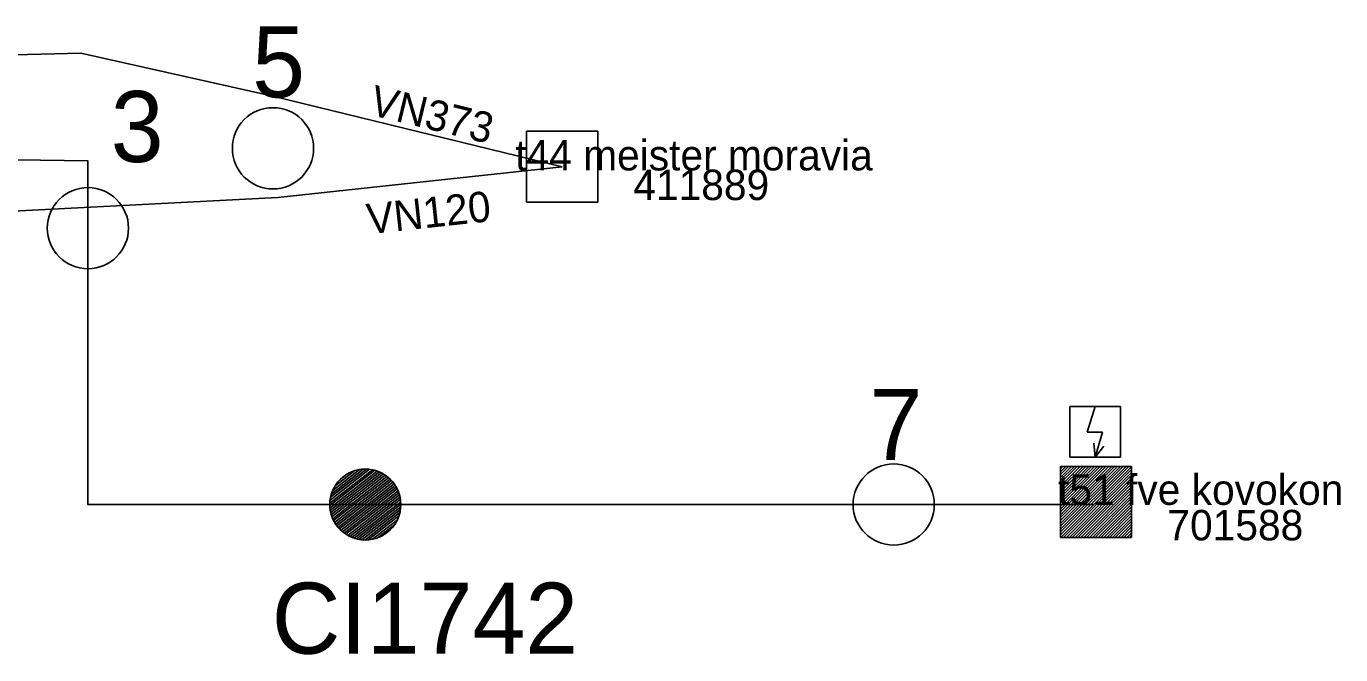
# Model space of a CAD drawing. Extents: x -541654 to -535721, y -1185255 to -1179094.
# Drawn here: x -539460 to -538812, y -1183468 to -1183158 of the extents above; entities that cross this region are included whole.
import ezdxf

# ---------------------------------------------------------------- set-up
doc = ezdxf.new("R2010")
doc.units = 0
for name, color, linetype in [('Default', 7, 'Continuous'), ('Vrstva 1', 7, 'Continuous'), ('Vrstva 2', 7, 'Continuous'), ('Vrstva 20', 7, 'Continuous'), ('Vrstva 3', 7, 'Continuous'), ('Vrstva 4', 7, 'Continuous'), ('Vrstva 47', 7, 'Continuous'), ('Vrstva 5', 7, 'Continuous')]:
    doc.layers.add(name, color=color, linetype=linetype)

# ---------------------------------------------------------------- blocks, each defined once
blk = doc.blocks.new('PS700')
at = {"layer": 'Vrstva 47'}
for points in [[(12.48, 12.51), (-12.52, 12.51)], [(-12.52, 12.51), (-12.52, -12.49)], [(-0.02, 12.51), (-3.96, -0.19)], [(12.48, -12.49), (12.48, 12.51)], [(-3.96, -0.19), (3.52, -0.19)], [(-0.02, -12.49), (-0.71, -5.7)], [(3.52, -0.19), (-0.02, -12.49)], [(-12.52, -12.49), (12.48, -12.49)], [(-0.02, -12.49), (4.31, -7.08)]]:
    blk.add_lwpolyline(points, dxfattribs=at)
blk = doc.blocks.new('PS140')
at = {"layer": 'Default'}
for p, q in [((-17.49, -0.01), (0.01, 17.49)), ((-17.43, -1.37), (1.37, 17.43)), ((-17.42, 1.47), (-1.47, 17.42)), ((-17.29, -2.63), (2.63, 17.29)), ((-17.21, 3.1), (-3.1, 17.21)), ((-17.06, -3.82), (3.82, 17.06)), ((-16.77, -4.95), (4.95, 16.77)), ((-16.77, 4.95), (-4.95, 16.77)), ((-16.42, -6.01), (6.01, 16.42)), ((-16.02, -7.02), (7.02, 16.02)), ((-15.93, 7.2), (-7.2, 15.93)), ((-15.56, -7.98), (7.98, 15.56)), ((-15.06, -8.89), (8.89, 15.06)), ((-14.51, -9.76), (9.76, 14.51)), ((-13.92, -10.58), (10.58, 13.92)), ((-13.75, 10.8), (-10.8, 13.75)), ((-13.29, -11.36), (11.36, 13.29)), ((-12.62, -12.11), (12.11, 12.62)), ((-11.91, -12.81), (12.81, 11.91)), ((-11.15, -13.47), (13.47, 11.15)), ((-10.36, -14.09), (14.09, 10.36)), ((-9.52, -14.67), (14.67, 9.52)), ((-8.64, -15.2), (15.2, 8.64)), ((-7.72, -15.69), (15.69, 7.72)), ((-6.74, -16.13), (16.13, 6.74)), ((-5.72, -16.52), (16.52, 5.72)), ((-4.64, -16.86), (16.86, 4.64)), ((-3.5, -17.13), (17.13, 3.5)), ((-2.29, -17.34), (17.34, 2.29)), ((-1, -17.46), (17.46, 1)), ((0.39, -17.48), (17.48, -0.39)), ((1.91, -17.38), (17.38, -1.91)), ((3.59, -17.11), (17.11, -3.59)), ((5.53, -16.59), (16.59, -5.53)), ((7.96, -15.57), (15.57, -7.96))]:
    blk.add_line(p, q, dxfattribs=at)
blk.add_circle((0, 0), 17.49, dxfattribs=at)
blk = doc.blocks.new('PS800')
at = {"layer": 'Vrstva 2'}
blk.add_circle((0, -0.01), 20, dxfattribs=at)
blk = doc.blocks.new('PS651')
at = {"layer": 'Vrstva 20'}
for points in [[(17.5, 17.5), (-17.5, 17.5)], [(-17.5, 17.5), (-17.5, -17.5)], [(17.5, -17.5), (17.5, 17.5)], [(-17.5, -17.5), (17.5, -17.5)]]:
    blk.add_lwpolyline(points, dxfattribs=at)
blk = doc.blocks.new('PS631')
at = {"layer": 'Default'}
for p, q in [((-16.61, -14.95), (17.07, 18.74)), ((-16.61, -13.53), (15.66, 18.74)), ((-16.61, -12.12), (14.24, 18.74)), ((-16.61, -10.71), (12.83, 18.74)), ((-16.61, -9.29), (11.41, 18.74)), ((-16.61, -7.88), (10, 18.74)), ((-16.61, -6.46), (8.59, 18.74)), ((-16.61, -5.05), (7.17, 18.74)), ((-16.61, -3.63), (5.76, 18.74)), ((-16.61, -2.22), (4.34, 18.74)), ((-16.61, -0.81), (2.93, 18.74)), ((-16.61, 0.61), (1.51, 18.74)), ((-16.61, 2.02), (0.1, 18.74)), ((-16.61, 3.44), (-1.31, 18.74)), ((-16.61, 4.85), (-2.73, 18.74)), ((-16.61, 6.27), (-4.14, 18.74)), ((-16.61, 7.68), (-5.56, 18.74)), ((-16.61, 9.09), (-6.97, 18.74)), ((-16.61, 10.51), (-8.38, 18.74)), ((-16.61, 11.92), (-9.8, 18.74)), ((-16.61, 13.34), (-11.21, 18.74)), ((-16.61, 14.75), (-12.63, 18.74)), ((-16.61, 16.16), (-14.04, 18.74)), ((-16.61, 17.58), (-15.46, 18.74)), ((-16.51, -16.26), (18.39, 18.64)), ((-15.1, -16.26), (18.39, 17.22)), ((-13.69, -16.26), (18.39, 15.81)), ((-12.27, -16.26), (18.39, 14.39)), ((-10.86, -16.26), (18.39, 12.98)), ((-9.44, -16.26), (18.39, 11.57)), ((-8.03, -16.26), (18.39, 10.15)), ((-6.62, -16.26), (18.39, 8.74)), ((-5.2, -16.26), (18.39, 7.32)), ((-3.79, -16.26), (18.39, 5.91)), ((-2.37, -16.26), (18.39, 4.5)), ((-0.96, -16.26), (18.39, 3.08)), ((0.46, -16.26), (18.39, 1.67)), ((1.87, -16.26), (18.39, 0.25)), ((3.28, -16.26), (18.39, -1.16)), ((4.7, -16.26), (18.39, -2.58)), ((6.11, -16.26), (18.39, -3.99)), ((7.53, -16.26), (18.39, -5.4)), ((8.94, -16.26), (18.39, -6.82)), ((10.36, -16.26), (18.39, -8.23)), ((11.77, -16.26), (18.39, -9.65)), ((13.18, -16.26), (18.39, -11.06)), ((14.6, -16.26), (18.39, -12.48)), ((16.01, -16.26), (18.39, -13.89)), ((17.43, -16.26), (18.39, -15.3))]:
    blk.add_line(p, q, dxfattribs=at)
for points in [[(-16.61, 18.74), (-16.61, -16.26)], [(18.39, 18.74), (-16.61, 18.74)], [(-16.61, 18.74), (-16.61, -16.26)], [(18.39, -16.26), (18.39, 18.74)], [(-16.61, -16.26), (18.39, -16.26)]]:
    blk.add_lwpolyline(points, dxfattribs=at)

msp = doc.modelspace()

# ---------------------------------------------------------------- linework, layer by layer
at = {"layer": 'Vrstva 1'}
for points in [[(-539754.08, -1183179.55), (-539432.97, -1183171.4), (-539338.48, -1183192.57)], [(-539338.48, -1183192.57), (-539195.96, -1183227.41)], [(-539663.24, -1183221.23), (-539429.55, -1183224.54), (-539429.55, -1183393.81), (-539292.92, -1183393.81)], [(-539335.94, -1183242.51), (-539195.96, -1183227.41)], [(-539666.79, -1183259.63), (-539335.94, -1183242.51)], [(-539292.92, -1183393.81), (-539166.67, -1183393.81)], [(-539166.67, -1183393.81), (-539032.63, -1183393.81)], [(-539032.63, -1183393.81), (-538933.84, -1183393.81)]]:
    msp.add_lwpolyline(points, dxfattribs=at)

# ---------------------------------------------------------------- block references
at = {"layer": 'Vrstva 2', "rotation": -6.948050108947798}
msp.add_blockref('PS140', (-539292.92, -1183393.81), dxfattribs=at)
at = {"layer": 'Vrstva 3'}
for name, p in [('PS651', (-539195.96, -1183227.41)), ('PS631', (-538933.84, -1183393.81))]:
    msp.add_blockref(name, p, dxfattribs=at)
at = {"layer": 'Vrstva 4'}
msp.add_blockref('PS700', (-538933.37, -1183357.95), dxfattribs=at)
at = {"layer": 'Vrstva 5'}
for p, rotation in [((-539338.39, -1183218.29), 4.80739434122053), ((-539429.55, -1183257.64), -14.14605001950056), ((-539032.63, -1183393.81), -7.214772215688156)]:
    msp.add_blockref('PS800', p, dxfattribs=dict(at, rotation=rotation))

# ---------------------------------------------------------------- texts
at = {"layer": 'Vrstva 1'}
for s, rotation, p in [('VN373', 346.262, (-539291.59, -1183201.58)), ('VN120', 6.155, (-539291.46, -1183260.7))]:
    msp.add_text(s, height=15, rotation=rotation, dxfattribs=at).set_placement(p)
at = {"layer": 'Vrstva 2'}
msp.add_text('CI1742', height=35, dxfattribs=at).set_placement((-539339, -1183467.32))
at = {"layer": 'Vrstva 3'}
for s, p in [('t44 meister moravia', (-539219.07, -1183229.2)), ('411889', (-539160.9, -1183243.81)), ('t51 fve kovokon', (-538951.66, -1183393.99)), ('701588', (-538897.83, -1183411.47))]:
    msp.add_text(s, height=15, dxfattribs=at).set_placement(p)
at = {"layer": 'Vrstva 5'}
for s, p in [('5', (-539348.63, -1183193.18)), ('3', (-539418.3, -1183225.07)), ('7', (-539044.59, -1183371.91))]:
    msp.add_text(s, height=35, dxfattribs=at).set_placement(p)

doc.saveas('drawing.dxf')
